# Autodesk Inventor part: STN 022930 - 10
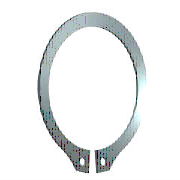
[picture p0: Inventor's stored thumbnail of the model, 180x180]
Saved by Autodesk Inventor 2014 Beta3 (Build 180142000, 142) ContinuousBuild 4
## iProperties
Created: 2010-02
Part Number: STN 022930 - 10
Material: Steel, Mild
Description: Retaining rings for shaft
Document SubType Name: Modeling
Standard: STN 022930
Designer: Thom Tremblay
Standards Organization: STN
Language: en-US
Size Designation: 10
Categories: <MemberInstance><Categories><Category DisplayName="Shaft Parts" InternalName="7f7aeb1f-a693-4053-b835-cee3144e0d98" Mnemonic="SHFT"><Category DisplayName="Circl
Density: 7.86 g/cm^3
Appearance: Steel
IsCustomPart: 0
Author: Thom Tremblay
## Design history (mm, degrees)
node "WorkPlane1"
workplane "Work Plane2"
node "WorkPlane2"
node "Sketch1"
node "WorkPoint1"
node "WorkAxis1"
sketch "Sketch3"
  geometry: L1 (-0.75, -4.741)-(-0.75, -7.741) reference; L2 (-0.75, -7.741)-(-3.75, -7.212) reference; 1 further point
  dimensions: "d30" = 1.2 distance from line of L1 point (-1.95, -6.159) (= 0.8 x Diam5); "d32" = 1.35 distance from line of L2 point (-1.95, -6.159) (= 0.45 x ParA)
hole "Hole1" sketch "Sketch3" at (-1.95, -6.159) diameter "d33" = 1.5 (= Diam5); stored, may be unused: countersink angle "d37" = 60 deg, drill point angle "d39" = 118 deg; dims "d34" = 6, "d35" = 4, "d36" = 2, "d38" = 8
sketch "Sketch4"
  geometry: L1 (0.75, -7.741)-(0.75, -4.741) reference; L2 (3.75, -7.212)-(0.75, -7.741) reference; 1 further point
  dimensions: "d41" = 1.2 distance from line of L1 point (1.95, -6.159) (= 0.8 x Diam5); "d43" = 1.35 distance from line of L2 point (1.95, -6.159) (= 0.45 x ParA)
hole "Hole2" sketch "Sketch4" at (1.95, -6.159) diameter "d44" = 1.5 (= Diam5); stored, may be unused: countersink angle "d48" = 60 deg, drill point angle "d50" = 118 deg; dims "d45" = 6, "d46" = 4, "d47" = 2, "d49" = 8
fillet "Fillet1" dims "d51" = 2.25 (= 1.5 x Diam5)
body "Solid1"
sketch "Sketch2"
  geometry: L1 (3.75, -7.212)-(3.75, -4.537); L2 (0.75, -7.741)-(3.75, -7.212); L3 (0.75, -4.741)-(0.75, -7.741); L4 (-0.75, -4.741)-(-0.75, -7.741); L5 (-0.75, -7.741)-(-3.75, -7.212); L6 (-3.75, -7.212)-(-3.75, -4.537); A1 r 4.8 centre (0, 0) between (0.75, -4.741) and (-0.75, -4.741); A2 r 6.2 centre (0, 0.4) between (3.75, -4.537) and (-3.75, -4.537); 1 further point
  constraints: 12 end point, 4 point on circle, 4 vertical, 2 centre point
  dimensions: "d2" = 4.8 radius of A1 (= 0.5 x Diam2); "d4" = 6.2 radius of A2 (= 0.166667 x ParA + 0.5 x Diam2 + 0.5 x b); "d6" = 0 horizontal distance of A2.centre A1.centre; "d8" = 0.75 horizontal distance of L3.start A1.centre (= 0.5 x Diam5); "d10" = 0.75 horizontal distance of L4.start A1.centre (= 0.5 x Diam5); "d12" = 3 distance of L4.start L4.end (= ParA); "d14" = 3 distance of L3.start L2.start (= ParA); "d16" = 80 deg angle of L2 L3; "d18" = 80 deg angle of L4 L5; "d20" = 3 horizontal distance of L4.start L6.end (= 2 x Diam5); "d22" = 3 horizontal distance of L1.start L3.start (= 2 x Diam5); "d24" = 0.4 distance of A1.centre A2.centre (= -msp_r2 + 0.5 x Diam2 + b); "d52" = 0 distance of point (0, 0) A1.centre; "d53" = 0 distance of A1.centre point (0, 0)
extrude "Extrusion1" new body sketch "Sketch2" distance "d25" = 1 (= ParS); taper "d26" = 0 deg
other parameters: "Diam5" = 1.5 [user parameter; used in 9 equation terms], "ParA" = 3 [user parameter; used in 6 equation terms], "b" = 1.8 [user parameter; used in 3 equation terms], "ParS" = 1 [user parameter; used in 2 equation terms], "Diam2" = 9.6 [user parameter; used in 4 equation terms], "msp_r2" = 6.2 (= 0.166667 x ParA + 0.5 x Diam2 + 0.5 x b) [user parameter; used in 1 equation term], "d0" = -1 (computed from ParS), "d1" = 14.3 (derived), "d3" = 0, "d5" = 0 (derived), "d7" = 1 (derived), "d9" = 1 (derived), "d11" = 4.8 (derived), "d13" = 4.8 (derived), "d15" = 80 deg (derived), "d17" = 80 deg (derived), "d19" = 4 (derived), "d21" = 4 (derived), "d23" = 0.95 (derived), "d27" = 0, "d28" = 0, "d29" = 1.6 (derived), "d31" = 2.16 (derived), "d40" = 1.6 (derived), "d42" = 2.16 (derived), "d55" = 0, "d56" = 0, "d57" = 0, "d58" = 0, "TEMPLATE" = 12.345 [user parameter]
